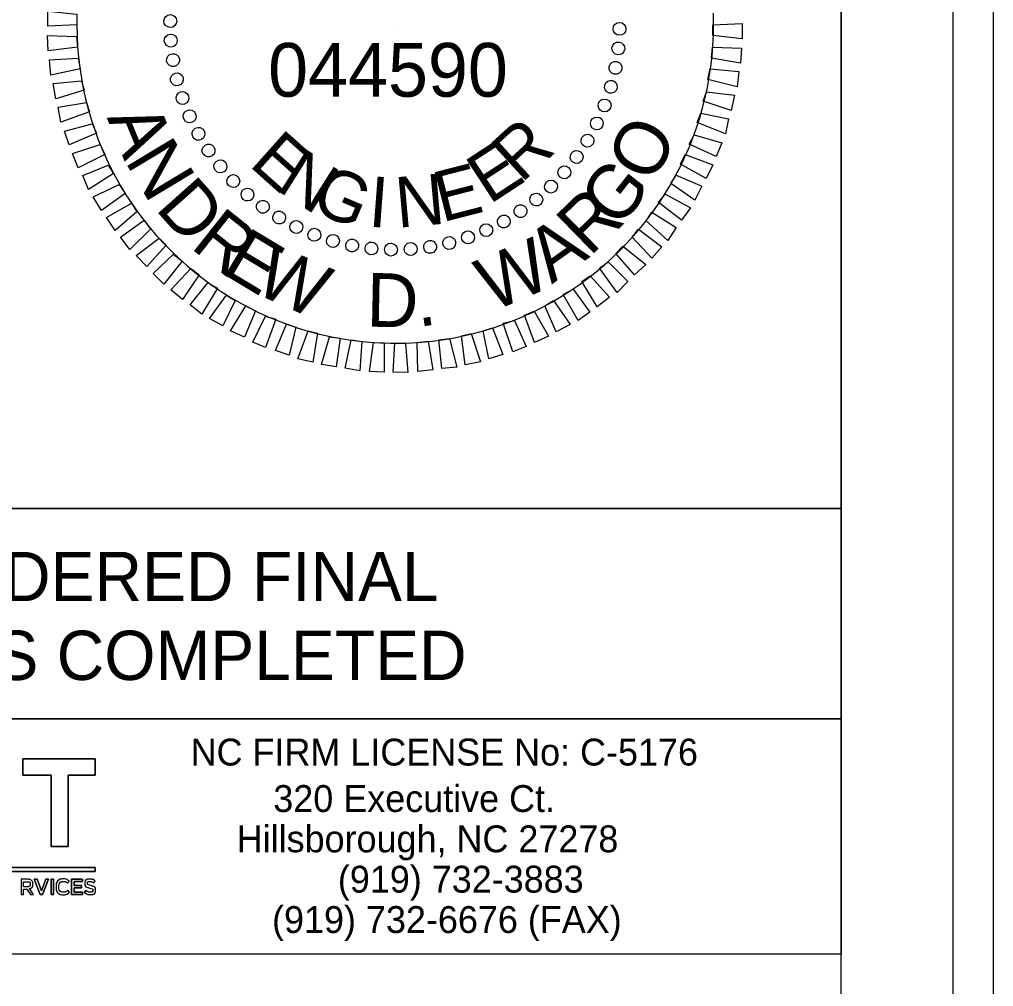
# Model space of a CAD drawing. Extents: x 3025871 to 3026431, y 707165 to 707825.
# Drawn here: x 3026258.31 to 3026274.62, y 707355 to 707371.19 of the extents above; entities that cross this region are included whole.
import ezdxf

# ---------------------------------------------------------------- set-up
doc = ezdxf.new("R2010")
doc.units = 0
for name, color, linetype in [('Old_Level_19', 7, 'Continuous'), ('Old_Level_39', 7, 'Continuous'), ('Prop DSN Text', 7, 'Continuous'), ('Sheet Block Title CELL', 7, 'Continuous'), ('Sheet Cutting Line CELL', 7, 'Continuous'), ('Typical Terminator CELL', 7, 'Continuous'), ('Typical Text ID Circle CELL', 7, 'Continuous')]:
    doc.layers.add(name, color=color, linetype=linetype)

msp = doc.modelspace()

# ---------------------------------------------------------------- linework, layer by layer
at = {"layer": 'Old_Level_19'}
for p, q in [((3026242.065, 707363.002), (3026272.071, 707363.002)), ((3026272.071, 707363), (3026272.071, 707359.475)), ((3026272.071, 707359.477), (3026242.065, 707359.477))]:
    msp.add_line(p, q, dxfattribs=at)
at = {"layer": 'Old_Level_39'}
msp.add_lwpolyline([(3026273.948, 707384.017), (3026023.973, 707384.017), (3026023.973, 707225.752), (3026273.948, 707225.752)], close=True, dxfattribs=at)
at = {"layer": 'Prop DSN Text'}
msp.add_arc((3026264.604, 707371.098), 5.331, 180.0118, 2.0847, dxfattribs=at)
at = {"layer": 'Sheet Block Title CELL'}
for p, q in [((3026260.833, 707371.164), (3026260.833, 707371.164)), ((3026264.598, 707371.097), (3026264.598, 707371.097)), ((3026268.363, 707371.029), (3026268.363, 707371.029)), ((3026260.841, 707370.834), (3026260.841, 707370.834)), ((3026268.341, 707370.699), (3026268.341, 707370.699)), ((3026260.886, 707370.512), (3026260.886, 707370.512)), ((3026268.288, 707370.377), (3026268.288, 707370.377)), ((3026260.946, 707370.182), (3026260.946, 707370.182)), ((3026268.221, 707370.062), (3026268.221, 707370.062)), ((3026261.036, 707369.867), (3026261.036, 707369.867)), ((3026268.116, 707369.747), (3026268.116, 707369.747)), ((3026261.156, 707369.567), (3026261.156, 707369.567)), ((3026267.981, 707369.447), (3026267.981, 707369.447)), ((3026261.306, 707369.274), (3026261.306, 707369.274)), ((3026267.831, 707369.154), (3026267.831, 707369.154)), ((3026261.478, 707368.989), (3026261.478, 707368.989)), ((3026267.643, 707368.884), (3026267.643, 707368.884)), ((3026261.666, 707368.727), (3026261.666, 707368.727)), ((3026267.441, 707368.622), (3026267.441, 707368.622)), ((3026261.891, 707368.479), (3026261.891, 707368.479)), ((3026267.216, 707368.389), (3026267.216, 707368.389)), ((3026262.123, 707368.254), (3026262.123, 707368.254)), ((3026266.968, 707368.164), (3026266.968, 707368.164)), ((3026262.386, 707368.052), (3026262.386, 707368.052)), ((3026266.706, 707367.977), (3026266.706, 707367.977)), ((3026262.656, 707367.864), (3026262.656, 707367.864)), ((3026266.421, 707367.804), (3026266.421, 707367.804)), ((3026262.948, 707367.714), (3026262.948, 707367.714)), ((3026266.128, 707367.654), (3026266.128, 707367.654)), ((3026263.248, 707367.579), (3026263.248, 707367.579)), ((3026263.563, 707367.474), (3026263.563, 707367.474)), ((3026265.828, 707367.534), (3026265.828, 707367.534)), ((3026263.878, 707367.407), (3026263.878, 707367.407)), ((3026264.201, 707367.354), (3026264.201, 707367.354)), ((3026264.531, 707367.332), (3026264.531, 707367.332)), ((3026264.861, 707367.339), (3026264.861, 707367.339)), ((3026265.183, 707367.384), (3026265.183, 707367.384)), ((3026265.513, 707367.444), (3026265.513, 707367.444))]:
    msp.add_line(p, q, dxfattribs=at)
for points in [[(3026259.273, 707371.097), (3026258.786, 707371.074), (3026258.786, 707371.329), (3026259.273, 707371.277)], [(3026269.923, 707371.097), (3026270.411, 707371.119), (3026270.411, 707370.864), (3026269.923, 707370.917)], [(3026259.281, 707370.722), (3026258.793, 707370.662), (3026258.778, 707370.917), (3026259.266, 707370.902)], [(3026269.916, 707370.722), (3026270.403, 707370.707), (3026270.388, 707370.459), (3026269.901, 707370.542)], [(3026259.326, 707370.362), (3026258.838, 707370.257), (3026258.816, 707370.512), (3026259.296, 707370.542)], [(3026269.878, 707370.362), (3026270.358, 707370.317), (3026270.328, 707370.062), (3026269.841, 707370.182)], [(3026259.393, 707370.002), (3026258.921, 707369.859), (3026258.876, 707370.114), (3026259.348, 707370.159)], [(3026269.818, 707369.979), (3026270.283, 707369.919), (3026270.231, 707369.664), (3026269.758, 707369.822)], [(3026259.483, 707369.642), (3026259.003, 707369.469), (3026258.958, 707369.717), (3026259.431, 707369.799)], [(3026269.721, 707369.619), (3026270.186, 707369.522), (3026270.133, 707369.274), (3026269.661, 707369.462)], [(3026259.603, 707369.282), (3026259.146, 707369.087), (3026259.063, 707369.319), (3026259.528, 707369.439)], [(3026269.608, 707369.259), (3026270.073, 707369.124), (3026269.976, 707368.892), (3026269.526, 707369.102)], [(3026259.738, 707368.929), (3026259.296, 707368.704), (3026259.198, 707368.944), (3026259.663, 707369.094)], [(3026269.458, 707368.929), (3026269.923, 707368.757), (3026269.811, 707368.524), (3026269.383, 707368.764)], [(3026259.888, 707368.607), (3026259.468, 707368.344), (3026259.371, 707368.577), (3026259.798, 707368.749)], [(3026269.308, 707368.584), (3026269.736, 707368.397), (3026269.623, 707368.164), (3026269.218, 707368.442)], [(3026260.083, 707368.277), (3026259.686, 707367.992), (3026259.543, 707368.217), (3026259.978, 707368.427)], [(3026260.278, 707367.969), (3026259.911, 707367.654), (3026259.768, 707367.872), (3026260.188, 707368.112)], [(3026269.128, 707368.262), (3026269.548, 707368.037), (3026269.398, 707367.827), (3026269.008, 707368.127)], [(3026268.903, 707367.962), (3026269.308, 707367.707), (3026269.166, 707367.489), (3026268.806, 707367.819)], [(3026260.503, 707367.677), (3026260.158, 707367.339), (3026260.001, 707367.542), (3026260.398, 707367.827)], [(3026268.678, 707367.677), (3026269.068, 707367.384), (3026268.903, 707367.189), (3026268.573, 707367.542)], [(3026260.766, 707367.407), (3026260.443, 707367.054), (3026260.263, 707367.234), (3026260.653, 707367.527)], [(3026268.416, 707367.392), (3026268.798, 707367.084), (3026268.611, 707366.912), (3026268.296, 707367.272)], [(3026261.036, 707367.144), (3026260.728, 707366.754), (3026260.548, 707366.934), (3026260.893, 707367.257)], [(3026261.321, 707366.912), (3026261.043, 707366.499), (3026260.848, 707366.664), (3026261.178, 707367.017)], [(3026268.168, 707367.129), (3026268.498, 707366.799), (3026268.318, 707366.619), (3026268.026, 707367.024)], [(3026267.868, 707366.897), (3026268.191, 707366.537), (3026267.988, 707366.379), (3026267.726, 707366.799)], [(3026261.628, 707366.687), (3026261.366, 707366.252), (3026261.171, 707366.409), (3026261.463, 707366.777)], [(3026267.583, 707366.672), (3026267.861, 707366.289), (3026267.666, 707366.147), (3026267.418, 707366.582)], [(3026261.921, 707366.484), (3026261.718, 707366.057), (3026261.493, 707366.184), (3026261.778, 707366.574)], [(3026267.253, 707366.484), (3026267.531, 707366.079), (3026267.298, 707365.959), (3026267.111, 707366.394)], [(3026262.266, 707366.312), (3026262.078, 707365.869), (3026261.846, 707365.974), (3026262.101, 707366.394)], [(3026262.603, 707366.169), (3026262.431, 707365.697), (3026262.221, 707365.787), (3026262.431, 707366.222)], [(3026266.931, 707366.304), (3026267.171, 707365.884), (3026266.938, 707365.779), (3026266.766, 707366.237)], [(3026262.941, 707366.034), (3026262.828, 707365.569), (3026262.596, 707365.644), (3026262.783, 707366.087)], [(3026266.233, 707366.027), (3026266.406, 707365.577), (3026266.173, 707365.509), (3026266.076, 707365.974)], [(3026266.601, 707366.147), (3026266.796, 707365.712), (3026266.571, 707365.622), (3026266.413, 707366.102)], [(3026263.301, 707365.937), (3026263.226, 707365.449), (3026262.971, 707365.509), (3026263.143, 707365.974)], [(3026263.683, 707365.854), (3026263.616, 707365.374), (3026263.368, 707365.412), (3026263.503, 707365.877)], [(3026265.513, 707365.847), (3026265.633, 707365.367), (3026265.386, 707365.344), (3026265.333, 707365.824)], [(3026265.873, 707365.929), (3026266.031, 707365.457), (3026265.776, 707365.404), (3026265.716, 707365.892)], [(3026264.043, 707365.794), (3026264.013, 707365.307), (3026263.766, 707365.352), (3026263.863, 707365.824)], [(3026264.418, 707365.772), (3026264.418, 707365.284), (3026264.171, 707365.292), (3026264.238, 707365.779)], [(3026264.778, 707365.764), (3026264.816, 707365.277), (3026264.568, 707365.284), (3026264.598, 707365.772)], [(3026265.153, 707365.802), (3026265.236, 707365.322), (3026264.981, 707365.292), (3026264.973, 707365.779)]]:
    msp.add_lwpolyline(points, close=True, dxfattribs=at)
for centre, major_axis in [((3026260.837, 707371.162), (-0.108, 0.002)), ((3026268.36, 707371.031), (0.108, -0.002)), ((3026260.845, 707370.834), (-0.108, -0.008)), ((3026268.34, 707370.703), (0.107, -0.011)), ((3026260.883, 707370.508), (-0.107, -0.017)), ((3026268.291, 707370.379), (0.106, -0.021)), ((3026260.948, 707370.186), (-0.105, -0.026)), ((3026268.215, 707370.06), (0.104, -0.03)), ((3026261.041, 707369.872), (-0.102, -0.035)), ((3026268.11, 707369.748), (0.101, -0.039)), ((3026261.161, 707369.566), (-0.0987, -0.0439)), ((3026267.98, 707369.447), (0.0971, -0.0473)), ((3026261.308, 707369.273), (-0.0945, -0.0524)), ((3026267.823, 707369.159), (0.0926, -0.0556)), ((3026261.479, 707368.993), (-0.0895, -0.0604)), ((3026267.642, 707368.885), (0.0874, -0.0635)), ((3026261.675, 707368.729), (-0.0839, -0.068)), ((3026261.892, 707368.483), (-0.0777, -0.075)), ((3026267.437, 707368.628), (0.0815, -0.0709)), ((3026267.212, 707368.39), (0.075, -0.0777)), ((3026262.13, 707368.257), (-0.0709, -0.0815)), ((3026266.966, 707368.173), (0.068, -0.0839)), ((3026262.387, 707368.053), (-0.0635, -0.0874)), ((3026262.661, 707367.872), (-0.0556, -0.0926)), ((3026266.702, 707367.978), (0.0604, -0.0895)), ((3026262.949, 707367.715), (-0.0473, -0.0971)), ((3026266.422, 707367.806), (0.0524, -0.0945)), ((3026263.25, 707367.584), (-0.039, -0.101)), ((3026265.823, 707367.54), (0.035, -0.102)), ((3026266.128, 707367.66), (0.0439, -0.0987)), ((3026263.561, 707367.48), (-0.03, -0.104)), ((3026263.88, 707367.404), (-0.021, -0.106)), ((3026264.205, 707367.355), (-0.011, -0.107)), ((3026265.187, 707367.381), (0.017, -0.107)), ((3026265.508, 707367.446), (0.026, -0.105)), ((3026264.533, 707367.335), (-0.002, -0.108)), ((3026264.861, 707367.344), (0.008, -0.108))]:
    msp.add_ellipse(centre, major_axis=major_axis, ratio=0.999708, dxfattribs=at)
at = {"layer": 'Sheet Cutting Line CELL'}
for points in [[(3026272.073, 707383.635), (3026047.073, 707383.635), (3026047.073, 707226.135), (3026272.073, 707226.135)], [(3026257.073, 707379.877), (3026272.073, 707379.877), (3026272.073, 707363.002), (3026257.073, 707363.002)]]:
    msp.add_lwpolyline(points, close=True, dxfattribs=at)
at = {"layer": 'Typical Terminator CELL'}
msp.add_lwpolyline([(3026274.623, 707387.385), (3026022.023, 707387.385), (3026022.023, 707222.385), (3026274.623, 707222.385)], close=True, dxfattribs=at)
at = {"layer": 'Typical Text ID Circle CELL'}
for p, q in [((3026258.493, 707356.711), (3026258.493, 707356.71)), ((3026258.537, 707356.713), (3026258.537, 707356.714)), ((3026259.118, 707356.726), (3026259.145, 707356.759)), ((3026259.405, 707356.724), (3026259.405, 707356.723)), ((3026259.448, 707356.727), (3026259.448, 707356.728)), ((3026259.555, 707356.732), (3026259.578, 707356.766)), ((3026258.923, 707356.667), (3026258.923, 707356.666)), ((3026258.968, 707356.667), (3026258.968, 707356.667)), ((3026259.147, 707356.58), (3026259.119, 707356.609)), ((3026259.421, 707356.608), (3026259.396, 707356.576)), ((3026259.542, 707356.608), (3026259.542, 707356.607)), ((3026259.585, 707356.612), (3026259.585, 707356.612))]:
    msp.add_line(p, q, dxfattribs=at)
msp.add_lwpolyline([(3026242.065, 707359.477), (3026272.074, 707359.477), (3026272.074, 707355.539), (3026242.065, 707355.539)], close=True, dxfattribs=at)
for points in [[(3026259.58, 707358.809), (3026259.58, 707358.538), (3026259.124, 707358.538), (3026259.124, 707357.34), (3026258.842, 707357.34), (3026258.842, 707358.538), (3026258.365, 707358.538), (3026258.365, 707358.809), (3026259.58, 707358.809)], [(3026258.365, 707358.809), (3026258.365, 707358.538), (3026258.842, 707358.538), (3026258.842, 707357.34), (3026259.124, 707357.34), (3026259.124, 707358.538), (3026259.58, 707358.538), (3026259.58, 707358.809), (3026258.365, 707358.809)], [(3026259.58, 707356.924), (3026252.749, 707356.924), (3026252.749, 707356.992), (3026259.58, 707356.992), (3026259.58, 707356.924)], [(3026259.58, 707356.992), (3026252.749, 707356.992), (3026252.749, 707356.924), (3026259.58, 707356.924), (3026259.58, 707356.992)], [(3026258.446, 707356.794), (3026258.337, 707356.794), (3026258.337, 707356.539), (3026258.38, 707356.539), (3026258.38, 707356.628), (3026258.434, 707356.628), (3026258.494, 707356.539), (3026258.545, 707356.539), (3026258.479, 707356.636)], [(3026258.443, 707356.668), (3026258.38, 707356.668), (3026258.38, 707356.753), (3026258.442, 707356.753)], [(3026258.558, 707356.794), (3026258.605, 707356.794), (3026258.679, 707356.598), (3026258.753, 707356.794), (3026258.799, 707356.794), (3026258.698, 707356.537), (3026258.66, 707356.537), (3026258.558, 707356.794)], [(3026258.66, 707356.537), (3026258.698, 707356.537), (3026258.799, 707356.794), (3026258.753, 707356.794), (3026258.679, 707356.598), (3026258.605, 707356.794), (3026258.558, 707356.794), (3026258.66, 707356.537)], [(3026258.84, 707356.794), (3026258.883, 707356.794), (3026258.883, 707356.539), (3026258.84, 707356.539), (3026258.84, 707356.794)], [(3026258.84, 707356.539), (3026258.883, 707356.539), (3026258.883, 707356.794), (3026258.84, 707356.794), (3026258.84, 707356.539)], [(3026259.185, 707356.794), (3026259.366, 707356.794), (3026259.366, 707356.754), (3026259.228, 707356.754), (3026259.228, 707356.688), (3026259.351, 707356.688), (3026259.351, 707356.648), (3026259.228, 707356.648), (3026259.228, 707356.579), (3026259.368, 707356.579), (3026259.368, 707356.539), (3026259.185, 707356.539), (3026259.185, 707356.794)], [(3026259.185, 707356.539), (3026259.368, 707356.539), (3026259.368, 707356.579), (3026259.228, 707356.579), (3026259.228, 707356.648), (3026259.351, 707356.648), (3026259.351, 707356.688), (3026259.228, 707356.688), (3026259.228, 707356.754), (3026259.366, 707356.754), (3026259.366, 707356.794), (3026259.185, 707356.794), (3026259.185, 707356.539)]]:
    msp.add_lwpolyline(points, dxfattribs=at)
for points, degree in [([(3026258.337, 707356.794), (3026258.337, 707356.794), (3026258.446, 707356.794), (3026258.446, 707356.794), (3026258.477, 707356.794), (3026258.501, 707356.785), (3026258.516, 707356.769), (3026258.529, 707356.755), (3026258.537, 707356.736), (3026258.537, 707356.714), (3026258.537, 707356.714), (3026258.537, 707356.713), (3026258.537, 707356.713), (3026258.537, 707356.671), (3026258.513, 707356.646), (3026258.479, 707356.636), (3026258.479, 707356.636), (3026258.545, 707356.539), (3026258.545, 707356.539), (3026258.545, 707356.539), (3026258.494, 707356.539), (3026258.494, 707356.539), (3026258.494, 707356.539), (3026258.434, 707356.628), (3026258.434, 707356.628), (3026258.434, 707356.628), (3026258.38, 707356.628), (3026258.38, 707356.628), (3026258.38, 707356.628), (3026258.38, 707356.539), (3026258.38, 707356.539), (3026258.38, 707356.539), (3026258.337, 707356.539), (3026258.337, 707356.539), (3026258.337, 707356.539), (3026258.337, 707356.794), (3026258.337, 707356.794)], 3), ([(3026258.443, 707356.668), (3026258.473, 707356.668), (3026258.493, 707356.685), (3026258.493, 707356.71), (3026258.493, 707356.71), (3026258.493, 707356.711), (3026258.493, 707356.711), (3026258.493, 707356.739), (3026258.474, 707356.753), (3026258.442, 707356.753), (3026258.442, 707356.753), (3026258.38, 707356.753), (3026258.38, 707356.753), (3026258.38, 707356.753), (3026258.38, 707356.668), (3026258.38, 707356.668), (3026258.38, 707356.668), (3026258.443, 707356.668), (3026258.443, 707356.668)], 3), ([(3026258.442, 707356.753), (3026258.474, 707356.753), (3026258.493, 707356.739), (3026258.493, 707356.711)], 2), ([(3026258.493, 707356.71), (3026258.493, 707356.685), (3026258.473, 707356.668), (3026258.443, 707356.668)], 2), ([(3026258.537, 707356.714), (3026258.537, 707356.736), (3026258.529, 707356.755), (3026258.516, 707356.769), (3026258.501, 707356.785), (3026258.477, 707356.794), (3026258.446, 707356.794)], 3), ([(3026258.479, 707356.636), (3026258.513, 707356.646), (3026258.537, 707356.671), (3026258.537, 707356.713)], 2), ([(3026258.923, 707356.666), (3026258.923, 707356.666), (3026258.923, 707356.667), (3026258.923, 707356.667), (3026258.923, 707356.739), (3026258.975, 707356.799), (3026259.049, 707356.799), (3026259.094, 707356.799), (3026259.122, 707356.782), (3026259.145, 707356.759), (3026259.145, 707356.759), (3026259.118, 707356.726), (3026259.118, 707356.726), (3026259.098, 707356.745), (3026259.077, 707356.757), (3026259.049, 707356.757), (3026259.003, 707356.757), (3026258.968, 707356.717), (3026258.968, 707356.667), (3026258.968, 707356.667), (3026258.968, 707356.667), (3026258.968, 707356.667), (3026258.968, 707356.617), (3026259.002, 707356.576), (3026259.049, 707356.576), (3026259.079, 707356.576), (3026259.098, 707356.589), (3026259.119, 707356.609), (3026259.119, 707356.609), (3026259.147, 707356.58), (3026259.147, 707356.58), (3026259.121, 707356.552), (3026259.093, 707356.535), (3026259.048, 707356.535), (3026258.976, 707356.535), (3026258.923, 707356.593), (3026258.923, 707356.666)], 3), ([(3026259.145, 707356.759), (3026259.122, 707356.782), (3026259.094, 707356.799), (3026259.049, 707356.799), (3026258.975, 707356.799), (3026258.923, 707356.739), (3026258.923, 707356.667)], 3), ([(3026258.968, 707356.667), (3026258.968, 707356.717), (3026259.003, 707356.757), (3026259.049, 707356.757), (3026259.077, 707356.757), (3026259.098, 707356.745), (3026259.118, 707356.726)], 3), ([(3026259.396, 707356.576), (3026259.396, 707356.576), (3026259.421, 707356.608), (3026259.421, 707356.608), (3026259.445, 707356.587), (3026259.469, 707356.575), (3026259.499, 707356.575), (3026259.525, 707356.575), (3026259.542, 707356.588), (3026259.542, 707356.607), (3026259.542, 707356.607), (3026259.542, 707356.608), (3026259.542, 707356.608), (3026259.542, 707356.626), (3026259.532, 707356.636), (3026259.487, 707356.647), (3026259.435, 707356.66), (3026259.405, 707356.676), (3026259.405, 707356.723), (3026259.405, 707356.723), (3026259.405, 707356.724), (3026259.405, 707356.724), (3026259.405, 707356.768), (3026259.44, 707356.798), (3026259.489, 707356.798), (3026259.525, 707356.798), (3026259.553, 707356.787), (3026259.578, 707356.766), (3026259.578, 707356.766), (3026259.555, 707356.732), (3026259.555, 707356.732), (3026259.533, 707356.749), (3026259.511, 707356.758), (3026259.488, 707356.758), (3026259.463, 707356.758), (3026259.448, 707356.745), (3026259.448, 707356.728), (3026259.448, 707356.728), (3026259.448, 707356.727), (3026259.448, 707356.727), (3026259.448, 707356.708), (3026259.46, 707356.699), (3026259.507, 707356.687), (3026259.558, 707356.674), (3026259.585, 707356.655), (3026259.585, 707356.612), (3026259.585, 707356.612), (3026259.585, 707356.612), (3026259.585, 707356.612), (3026259.585, 707356.564), (3026259.549, 707356.536), (3026259.498, 707356.536), (3026259.46, 707356.536), (3026259.425, 707356.549), (3026259.396, 707356.576)], 3), ([(3026259.578, 707356.766), (3026259.553, 707356.787), (3026259.525, 707356.798), (3026259.489, 707356.798), (3026259.44, 707356.798), (3026259.405, 707356.768), (3026259.405, 707356.724)], 3), ([(3026259.405, 707356.723), (3026259.405, 707356.676), (3026259.435, 707356.66), (3026259.487, 707356.647), (3026259.532, 707356.636), (3026259.542, 707356.626), (3026259.542, 707356.608)], 3), ([(3026259.448, 707356.728), (3026259.448, 707356.745), (3026259.463, 707356.758), (3026259.488, 707356.758), (3026259.511, 707356.758), (3026259.533, 707356.749), (3026259.555, 707356.732)], 3), ([(3026259.585, 707356.612), (3026259.585, 707356.655), (3026259.558, 707356.674), (3026259.507, 707356.687), (3026259.46, 707356.699), (3026259.448, 707356.708), (3026259.448, 707356.727)], 3), ([(3026258.923, 707356.666), (3026258.923, 707356.593), (3026258.976, 707356.535), (3026259.048, 707356.535), (3026259.093, 707356.535), (3026259.121, 707356.552), (3026259.147, 707356.58)], 3), ([(3026259.119, 707356.609), (3026259.098, 707356.589), (3026259.079, 707356.576), (3026259.049, 707356.576), (3026259.002, 707356.576), (3026258.968, 707356.617), (3026258.968, 707356.667)], 3), ([(3026259.396, 707356.576), (3026259.425, 707356.549), (3026259.46, 707356.536), (3026259.498, 707356.536), (3026259.549, 707356.536), (3026259.585, 707356.564), (3026259.585, 707356.612)], 3), ([(3026259.542, 707356.607), (3026259.542, 707356.588), (3026259.525, 707356.575), (3026259.499, 707356.575), (3026259.469, 707356.575), (3026259.445, 707356.587), (3026259.421, 707356.608)], 3)]:
    msp.add_open_spline(points, degree=degree, dxfattribs=at)

# ---------------------------------------------------------------- texts
at = {"layer": 'Old_Level_19'}
for s, p in [('DOCUMENT NOT CONSIDERED FINAL', (3026245.226, 707361.45)), ('UNLESS ALL SIGNATURES COMPLETED', (3026244.465, 707360.13))]:
    msp.add_text(s, height=0.825, rotation=360, dxfattribs=at).set_placement(p)
at = {"layer": 'Sheet Block Title CELL'}
msp.add_text('044590', height=0.8997, dxfattribs=at).set_placement((3026262.475, 707369.895))
for s, height, rotation, p in [('A', 0.9, 292.2016, (3026259.771, 707369.547)), ('R', 0.846, 42.4814, (3026266.713, 707368.434)), ('O', 0.9, 62.5158, (3026268.913, 707368.416)), ('E', 0.846, 318.2769, (3026262.138, 707368.749)), ('N', 0.9, 301.0323, (3026260.066, 707368.823)), ('E', 0.846, 33.1241, (3026266.181, 707368.082)), ('N', 0.846, 327.634, (3026262.588, 707368.344)), ('E', 0.846, 14.4118, (3026265.386, 707367.789)), ('G', 0.9, 51.8017, (3026268.34, 707367.662)), ('G', 0.846, 336.9902, (3026263.158, 707368.007)), ('N', 0.846, 5.0564, (3026264.643, 707367.699)), ('D', 0.9, 311.7464, (3026260.568, 707368.019)), ('I', 0.846, 355.7012, (3026264.141, 707367.722)), ('R', 0.9, 44.3296, (3026267.861, 707367.205)), ('R', 0.9, 321.6115, (3026261.155, 707367.373)), ('E', 0.9, 329.0836, (3026261.669, 707366.956)), ('A', 0.9, 35.4989, (3026267.225, 707366.751)), ('W', 0.9, 22.9785, (3026266.22, 707366.286)), ('W', 0.9, 336.1852, (3026262.204, 707366.625)), ('D', 0.9, 358.8948, (3026264.116, 707366.046)), ('.', 0.9, 8.7599, (3026264.989, 707366.037))]:
    msp.add_text(s, height=height, rotation=rotation, dxfattribs=at).set_placement(p)
at = {"layer": 'Typical Text ID Circle CELL'}
for s, p in [('NC FIRM LICENSE No: C-5176', (3026261.177, 707358.698)), ('320 Executive Ct.', (3026262.562, 707357.92)), ('Hillsborough, NC 27278', (3026261.949, 707357.245)), ('(919) 732-3883', (3026263.643, 707356.57)), ('(919) 732-6676 (FAX)', (3026262.541, 707355.894))]:
    msp.add_text(s, height=0.45013, rotation=360, dxfattribs=at).set_placement(p)

doc.saveas('drawing.dxf')
